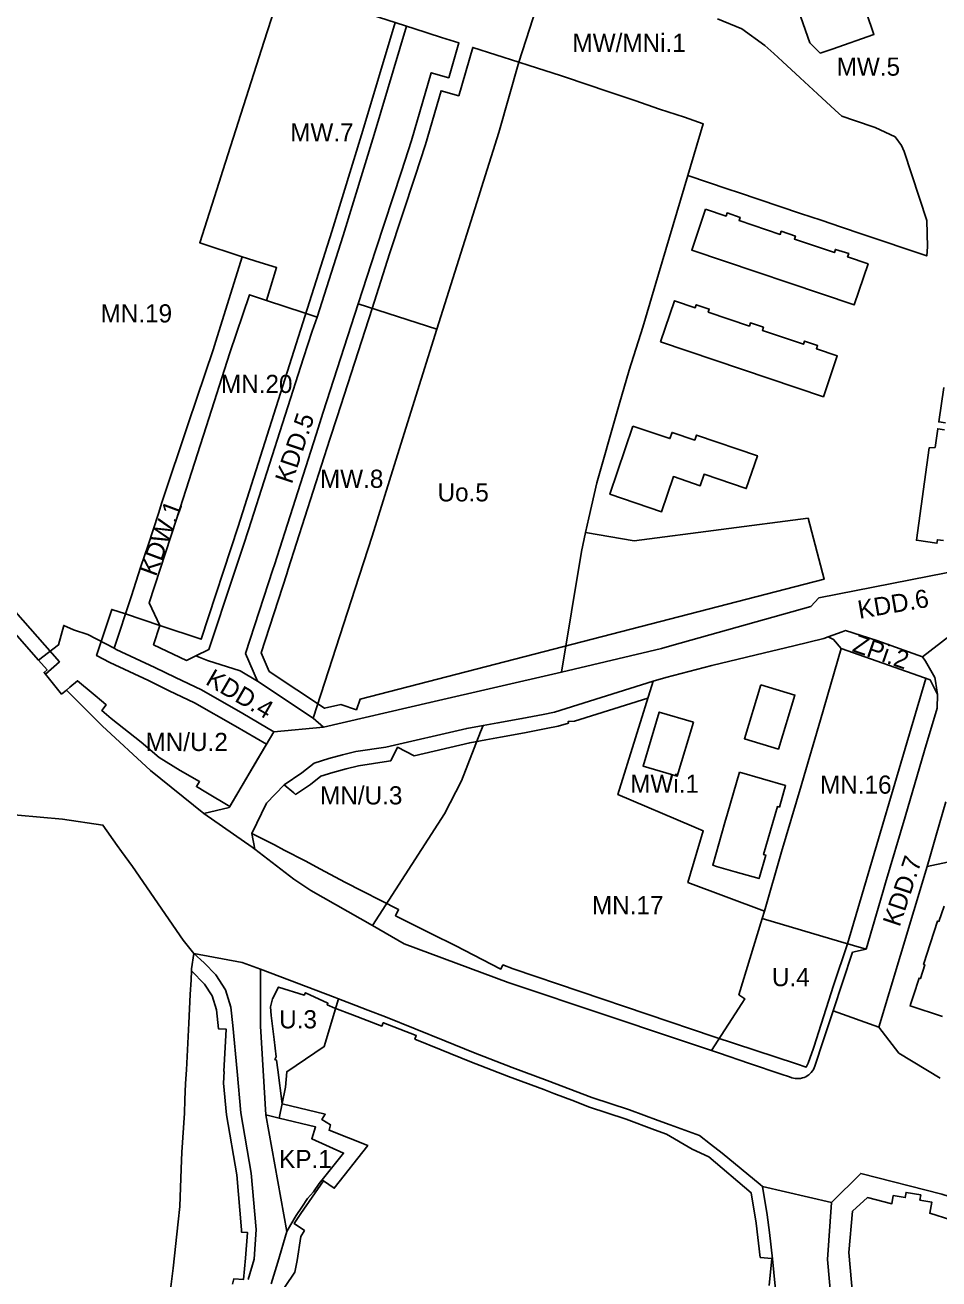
# Model space of a CAD drawing. Extents: x 7416797 to 7419013, y 5549660 to 5551534.
# Drawn here: x 7417362.3 to 7417614, y 5550279.7 to 5550624.8 of the extents above; entities that cross this region are included whole.
import ezdxf

# ---------------------------------------------------------------- set-up
doc = ezdxf.new("R2010")
doc.units = 0
for name, color, linetype in [('LIN_Linia Zabudowy Nieprzekraczalna', 7, 'Continuous'), ('LIN_Linia Zabudowy Obowiązujaca', 7, 'Continuous'), ('LIN_linie_rozgraniczajace', 7, 'Continuous'), ('TXT_Oznaczenia_przeznaczen', 7, 'Continuous')]:
    doc.layers.add(name, color=color, linetype=linetype)

msp = doc.modelspace()

# ---------------------------------------------------------------- linework, layer by layer
at = {"layer": 'LIN_Linia Zabudowy Nieprzekraczalna'}
msp.add_line((7417588.79, 5550371.98), (7417610.35, 5550444.97), dxfattribs=at)
for points in [[(7417399.46, 5550459.54), (7417410.81, 5550455.77), (7417421, 5550486.78), (7417446.8, 5550568.03), (7417455.32, 5550595.79), (7417464.2, 5550625.52)], [(7417498.33, 5550614.61), (7417485.58, 5550618.68), (7417481.74, 5550605.36), (7417476.89, 5550606.74), (7417472.57, 5550591.9), (7417469.74, 5550583.26), (7417462.71, 5550561.83), (7417457.87, 5550546.82), (7417448.23, 5550517.01), (7417446.27, 5550510.88), (7417434.79, 5550475.05), (7417434.37, 5550473.75), (7417427.33, 5550452.02), (7417429.56, 5550446.91), (7417444.81, 5550436.77), (7417449.3, 5550437.84), (7417453.57, 5550436.35), (7417454.55, 5550439.33), (7417582.39, 5550472.29), (7417577.96, 5550489.06), (7417530.06, 5550482.89), (7417516.68, 5550485.17)], [(7417349.45, 5550474.83), (7417371.77, 5550449.57), (7417367.92, 5550446.17), (7417372.39, 5550440.69), (7417373.7, 5550441.79), (7417374.69, 5550442.63), (7417376.78, 5550444.35), (7417381.11, 5550440.74), (7417383.89, 5550438.37), (7417384.67, 5550437.71), (7417383.44, 5550436.2), (7417386.07, 5550433.99), (7417394.27, 5550427.42), (7417399.24, 5550423.21), (7417405.06, 5550419.69), (7417410.36, 5550416.6), (7417409.51, 5550415.23), (7417412.12, 5550413.67), (7417418.66, 5550409.75), (7417426.51, 5550423.06), (7417428.77, 5550426.89), (7417420.29, 5550431.89), (7417409.01, 5550438.31), (7417402, 5550441.62), (7417396.28, 5550444.41), (7417385.68, 5550449.4), (7417382.03, 5550451.29), (7417386.18, 5550464), (7417389.97, 5550462.73)], [(7417533.84, 5550439.59), (7417513.62, 5550433.25), (7417511.91, 5550433.14), (7417511.94, 5550432.72), (7417509.13, 5550431.84), (7417505.81, 5550431.17), (7417499.86, 5550430.02), (7417493.25, 5550428.83), (7417489.2, 5550428.11), (7417484.75, 5550427.31), (7417469.44, 5550423.73), (7417464.89, 5550426.03), (7417463, 5550422.32), (7417462.38, 5550422.18), (7417454.13, 5550420.92), (7417450.7, 5550420.11), (7417447.08, 5550419.1), (7417443.8, 5550418.11), (7417440.92, 5550415.76), (7417436.8, 5550413.09), (7417436.3, 5550413.5), (7417433.63, 5550415.7), (7417428.79, 5550410.62), (7417424.77, 5550402.35), (7417430.99, 5550399.21), (7417433.68, 5550397.69), (7417439.47, 5550394.8), (7417443.69, 5550392.51), (7417450.4, 5550388.88), (7417465.18, 5550381.36), (7417464.34, 5550379.67), (7417474.4, 5550374.57), (7417480.79, 5550371.46), (7417493.34, 5550365), (7417493.91, 5550366.13), (7417496.71, 5550365.1), (7417552.06, 5550346.36), (7417574.77, 5550338.89), (7417577.41, 5550338.03), (7417577.95, 5550339.06), (7417579.39, 5550343.24), (7417579.48, 5550343.51), (7417584.95, 5550360.5), (7417588.79, 5550371.98)], [(7417419.43, 5550278.3), (7417419.84, 5550279.79), (7417422.43, 5550279.53), (7417423.01, 5550285.46), (7417423.58, 5550292.48), (7417421.91, 5550292.63), (7417421.95, 5550293.23), (7417420.59, 5550308.36), (7417417.79, 5550324.87), (7417416.99, 5550333.59), (7417417.19, 5550336.79), (7417417.07, 5550336.8), (7417417.74, 5550348.45), (7417417.51, 5550348.46), (7417415.6, 5550348.53), (7417415.01, 5550353.76), (7417413.88, 5550357.6), (7417411.72, 5550360.86), (7417408.15, 5550364.55)], [(7417567.25, 5550277.89), (7417567.95, 5550285.32), (7417564.76, 5550285.64), (7417563.64, 5550295.1), (7417562.22, 5550303.46), (7417550.62, 5550313.29), (7417545.99, 5550315.45), (7417538.96, 5550319.58), (7417535.69, 5550320.8), (7417527.84, 5550323.69), (7417517.5, 5550327.08), (7417513.58, 5550328.61), (7417507.96, 5550330.76), (7417505.14, 5550331.82), (7417495.47, 5550335.4), (7417484.81, 5550339.52), (7417476.89, 5550342.75), (7417469.67, 5550345.74), (7417470.06, 5550346.74), (7417461.03, 5550350.18), (7417460.93, 5550350.22), (7417460.59, 5550349.33), (7417452.44, 5550352.38), (7417447.62, 5550354.25), (7417445.51, 5550355.16), (7417445.71, 5550355.6), (7417439.5, 5550358.48), (7417439.21, 5550357.84), (7417432.07, 5550360.04), (7417430.42, 5550356.85), (7417429.89, 5550354.57), (7417430.1, 5550352.21), (7417430.9, 5550345.64), (7417431.48, 5550340.87), (7417431.13, 5550340.11), (7417431.6, 5550339.9), (7417431.92, 5550337.27), (7417433.1, 5550327.92), (7417444.97, 5550325.03), (7417444.04, 5550323.56), (7417446.42, 5550322.15), (7417446.02, 5550320.65), (7417456.69, 5550316.41), (7417447.45, 5550304.68), (7417444.47, 5550306.74), (7417438.23, 5550297.72), (7417436.39, 5550295), (7417439.26, 5550293.04), (7417438.23, 5550291.39), (7417437.22, 5550284.78), (7417436.59, 5550281.54), (7417431.12, 5550273.42)], [(7417692.43, 5550272.17), (7417611.45, 5550297.78), (7417611.98, 5550300.89), (7417608.73, 5550301.43), (7417608.96, 5550302.84), (7417604.93, 5550303.53), (7417604.7, 5550302.11), (7417601.39, 5550302.66), (7417601, 5550300.42), (7417594.29, 5550302.09), (7417590.14, 5550298.35), (7417589.15, 5550286.98), (7417595.98, 5550210.57)]]:
    msp.add_lwpolyline(points, dxfattribs=at)
at = {"layer": 'LIN_Linia Zabudowy Obowiązujaca'}
for points in [[(7417563.44, 5550678.69), (7417560.16, 5550677.49), (7417559.27, 5550674.67), (7417578.38, 5550619.91), (7417581.25, 5550617.11), (7417584.57, 5550618.16), (7417596.07, 5550622.21), (7417593.98, 5550628.2), (7417594.83, 5550628.5), (7417593.6, 5550632.03), (7417592.75, 5550631.73), (7417588.77, 5550643.17), (7417589.64, 5550643.47), (7417588.37, 5550647.07), (7417587.51, 5550646.77), (7417583.53, 5550658.19), (7417584.37, 5550658.48), (7417583.15, 5550662.08), (7417582.28, 5550661.78), (7417578.3, 5550673.18), (7417579.15, 5550673.48), (7417577.91, 5550677.07), (7417577.05, 5550676.77), (7417574.97, 5550682.74)], [(7417549.68, 5550574.13), (7417545.89, 5550562.86), (7417590.65, 5550547.78), (7417594.48, 5550559.07), (7417588.81, 5550560.98), (7417589.12, 5550561.9), (7417585.48, 5550563.06), (7417585.19, 5550562.19), (7417574.16, 5550565.9), (7417574.44, 5550566.72), (7417570.54, 5550568.05), (7417570.26, 5550567.21), (7417558.92, 5550571.02), (7417559.21, 5550571.88), (7417555.64, 5550573.09), (7417555.35, 5550572.22)], [(7417537.34, 5550537.61), (7417582.18, 5550522.53), (7417585.95, 5550533.8), (7417580.24, 5550535.73), (7417580.54, 5550536.61), (7417576.94, 5550537.83), (7417576.64, 5550536.95), (7417565.36, 5550540.76), (7417565.66, 5550541.64), (7417562.05, 5550542.84), (7417561.76, 5550541.98), (7417550.43, 5550545.81), (7417550.71, 5550546.63), (7417547.12, 5550547.83), (7417546.85, 5550547.02), (7417541.19, 5550548.93)], [(7417529.67, 5550514.43), (7417523.37, 5550495.67), (7417537.59, 5550490.86), (7417540.86, 5550500.54), (7417548.23, 5550498.04), (7417549.29, 5550501.19), (7417560.93, 5550497.25), (7417563.99, 5550506.27), (7417547.2, 5550511.95), (7417546.74, 5550510.59), (7417540.49, 5550512.7), (7417539.91, 5550511)], [(7417564.96, 5550443.22), (7417560.41, 5550428.41), (7417569.79, 5550425.55), (7417574.31, 5550440.42)], [(7417546.41, 5550432.95), (7417536.97, 5550435.72), (7417532.49, 5550420.86), (7417541.91, 5550418.08)], [(7417559.02, 5550419.16), (7417555.77, 5550407.86), (7417555.05, 5550405.31), (7417551.69, 5550393.58), (7417552.72, 5550393.26), (7417557.88, 5550391.77), (7417564.45, 5550389.92), (7417564.53, 5550390.33), (7417566.27, 5550396.36), (7417565.69, 5550396.53), (7417569.49, 5550409.73), (7417570.06, 5550409.57), (7417571.76, 5550415.53)]]:
    msp.add_lwpolyline(points, close=True, dxfattribs=at)
for points in [[(7417615.29, 5550525.03), (7417613.94, 5550515.58), (7417615.77, 5550515.34)], [(7417615.51, 5550513.42), (7417613.65, 5550513.7), (7417612.89, 5550508.59), (7417611.27, 5550508.44), (7417607.75, 5550483.01), (7417613.43, 5550482.2), (7417613.56, 5550483.14), (7417615.24, 5550482.91)], [(7417615.37, 5550382.35), (7417613.95, 5550378.12), (7417613.61, 5550378.2), (7417610.67, 5550369.12), (7417609.9, 5550366.77), (7417609.74, 5550366.26), (7417610.12, 5550366.14), (7417608.89, 5550362.38), (7417608.51, 5550362.5), (7417608.34, 5550361.98), (7417607.13, 5550358.24), (7417606.15, 5550355.26), (7417606.02, 5550354.87), (7417614.95, 5550351.97)]]:
    msp.add_lwpolyline(points, dxfattribs=at)
at = {"layer": 'LIN_linie_rozgraniczajace'}
for p, q in [((7417389.97, 5550462.73), (7417399.46, 5550459.54)), ((7417609.46, 5550450.96), (7417616.73, 5550456.52)), ((7417430.8, 5550430.33), (7417444.54, 5550431.61)), ((7417584.84, 5550353.48), (7417597.45, 5550348.99)), ((7417432.31, 5550323.99), (7417428.62, 5550324.89)), ((7417434.38, 5550292.78), (7417428.62, 5550324.89)), ((7417565.34, 5550305.12), (7417584.39, 5550300.76)), ((7417434.38, 5550292.78), (7417431.88, 5550284.37)), ((7417431.88, 5550284.37), (7417430.12, 5550278.34))]:
    msp.add_line(p, q, dxfattribs=at)
for points in [[(7417498.33, 5550614.61), (7417507.1, 5550641.98), (7417509.39, 5550649.12), (7417514.34, 5550663.31), (7417519.65, 5550678.48), (7417525.2, 5550694.12), (7417526.2, 5550697.62), (7417529.19, 5550708.08), (7417534.93, 5550728.18), (7417547.88, 5550768.74), (7417550.12, 5550775.76), (7417557.51, 5550797.22), (7417560.89, 5550807.03)], [(7417433.01, 5550635.5), (7417428.17, 5550620.35), (7417416.78, 5550584.76), (7417415.74, 5550581.53), (7417410.4, 5550564.88), (7417422.07, 5550561.06)], [(7417467.36, 5550624.51), (7417464.2, 5550625.52), (7417453.29, 5550629.02), (7417448.7, 5550630.48), (7417444.08, 5550631.96), (7417433.01, 5550635.5)], [(7417553, 5550626.52), (7417559.65, 5550623.75), (7417566.05, 5550619.22), (7417568.47, 5550616.99), (7417570.89, 5550614.76), (7417575.72, 5550610.32), (7417580.55, 5550605.87), (7417585.39, 5550601.42), (7417587.19, 5550599.75), (7417590.75, 5550598.56), (7417596.44, 5550596.64), (7417601.9, 5550594.07), (7417603.7, 5550591.63), (7417604.37, 5550590.06), (7417610.68, 5550571), (7417610.83, 5550563.76), (7417610.6, 5550561.27), (7417592.87, 5550567.25), (7417587.18, 5550569.16), (7417581.5, 5550571.07), (7417575.81, 5550572.99), (7417570.12, 5550574.9), (7417564.44, 5550576.82), (7417558.75, 5550578.73), (7417555.91, 5550579.69), (7417544.83, 5550583.42)], [(7417442.77, 5550544.39), (7417449.93, 5550566.94), (7417458.46, 5550594.73), (7417467.36, 5550624.51)], [(7417454.06, 5550548.05), (7417458.91, 5550563.07), (7417465.94, 5550584.51), (7417468.75, 5550593.08), (7417474.17, 5550611.67), (7417479, 5550610.3), (7417481.77, 5550619.9), (7417477.01, 5550621.43), (7417469.39, 5550623.87), (7417467.36, 5550624.51)], [(7417498.33, 5550614.61), (7417492.82, 5550595.2), (7417488.01, 5550580.14), (7417487.24, 5550577.68), (7417475.69, 5550541.12)], [(7417544.83, 5550583.42), (7417549.06, 5550597.67), (7417543.87, 5550599.42), (7417537.04, 5550601.71), (7417530.22, 5550604.02), (7417523.39, 5550606.31), (7417516.57, 5550608.61), (7417511.38, 5550610.36), (7417509.74, 5550610.89), (7417501.17, 5550613.69), (7417498.33, 5550614.61)], [(7417509.99, 5550446.76), (7417515.51, 5550479.9), (7417516.68, 5550485.17), (7417517.59, 5550489.23), (7417519.74, 5550498.8), (7417525.21, 5550517.86), (7417525.93, 5550520.36), (7417528.66, 5550529.84), (7417532.43, 5550541.7), (7417536.75, 5550556.24), (7417544.83, 5550583.42)], [(7417389.97, 5550462.73), (7417391.52, 5550467.48), (7417394.23, 5550475.81), (7417396.19, 5550481.64), (7417399.09, 5550490.36), (7417400.02, 5550493.38), (7417407.36, 5550515.34), (7417414.07, 5550535.41), (7417414.81, 5550537.81), (7417422.07, 5550561.06)], [(7417422.07, 5550561.06), (7417427.07, 5550559.42), (7417431.57, 5550558.06), (7417428.78, 5550549.04)], [(7417428.78, 5550549.04), (7417424.13, 5550550.58), (7417418.72, 5550534.57), (7417412.2, 5550514.27), (7417405.04, 5550491.97), (7417404.95, 5550491.69), (7417404.02, 5550488.85), (7417396.5, 5550465.82), (7417399.46, 5550459.54)], [(7417426.36, 5550444.23), (7417423.06, 5550451.81), (7417430.56, 5550474.98), (7417430.98, 5550476.28), (7417442.46, 5550512.1), (7417444.42, 5550518.23), (7417454.06, 5550548.05)], [(7417428.78, 5550549.04), (7417439.18, 5550545.59), (7417442.77, 5550544.39)], [(7417454.06, 5550548.05), (7417459.42, 5550546.33), (7417475.69, 5550541.12)], [(7417409.3, 5550451.18), (7417412.88, 5550452.95), (7417419.64, 5550473.14), (7417422.51, 5550481.7), (7417423.89, 5550485.91), (7417439.03, 5550533.23), (7417441.38, 5550540.57), (7417442.77, 5550544.39)], [(7417475.69, 5550541.12), (7417471.36, 5550527.4), (7417464.41, 5550505.06), (7417457.92, 5550484.19), (7417453.23, 5550469.76), (7417441.63, 5550434.08)], [(7417309.69, 5550514.65), (7417320.09, 5550502.64), (7417343.62, 5550475.48), (7417346.44, 5550472.2), (7417366.03, 5550450.02)], [(7417509.99, 5550446.76), (7417537.56, 5550453.2), (7417540.46, 5550454.02), (7417578.72, 5550464.83), (7417580.92, 5550467.15), (7417621.12, 5550475.03), (7417623.13, 5550478.14), (7417658.47, 5550485.31)], [(7417386.89, 5550453.28), (7417388.42, 5550457.98), (7417389.97, 5550462.73)], [(7417366.03, 5550450.02), (7417371.49, 5550454.21), (7417372.99, 5550459.59), (7417375.63, 5550458.33), (7417379.6, 5550457.06), (7417386.89, 5550453.28)], [(7417399.46, 5550459.54), (7417397.72, 5550454.26), (7417406.79, 5550449.94), (7417409.3, 5550451.18)], [(7417583.43, 5550456.4), (7417587.28, 5550457.8), (7417588.23, 5550458.14), (7417596.83, 5550455.4), (7417609.46, 5550450.96)], [(7417535.28, 5550444.24), (7417538.81, 5550445.29), (7417551.4, 5550448.59), (7417560.99, 5550450.86), (7417563.6, 5550451.48), (7417574.03, 5550453.97), (7417582.31, 5550455.98), (7417583.43, 5550456.4)], [(7417587.03, 5550453.21), (7417584.98, 5550455.75), (7417583.43, 5550456.4)], [(7417386.89, 5550453.28), (7417387.45, 5550452.99), (7417398.01, 5550448.02), (7417403.73, 5550445.23), (7417410.86, 5550441.86), (7417422.3, 5550435.35), (7417430.8, 5550430.33)], [(7417409.3, 5550451.18), (7417412.54, 5550449.92), (7417421.52, 5550447.06), (7417426.36, 5550444.23)], [(7417587.03, 5550453.21), (7417581.37, 5550433.64), (7417576.9, 5550418.31), (7417576.02, 5550415.4), (7417570.63, 5550397.24), (7417565.97, 5550380.91)], [(7417613.62, 5550440.55), (7417611.51, 5550444.56), (7417587.03, 5550453.21)], [(7417609.46, 5550450.96), (7417610.28, 5550449.7), (7417612.87, 5550445.28), (7417613.03, 5550444.27), (7417613.62, 5550440.55)], [(7417366.03, 5550450.02), (7417368.39, 5550447.35), (7417367.54, 5550446.63), (7417372.39, 5550440.69), (7417373.7, 5550441.79), (7417383.59, 5550431.94), (7417396.9, 5550419.68), (7417411.59, 5550407.8)], [(7417441.63, 5550434.08), (7417426.36, 5550444.23)], [(7417444.54, 5550431.61), (7417473.79, 5550438.34), (7417509.99, 5550446.76)], [(7417488.5, 5550432.05), (7417492.54, 5550432.77), (7417499.13, 5550433.95), (7417505.03, 5550435.09), (7417508.13, 5550435.72), (7417535.28, 5550444.24)], [(7417535.28, 5550444.24), (7417525.58, 5550413.03), (7417545.85, 5550404.38), (7417549.06, 5550403.01), (7417544.85, 5550388.87), (7417565.97, 5550380.91)], [(7417593.91, 5550370.46), (7417598.54, 5550386.21), (7417599.28, 5550388.72), (7417604.69, 5550406.92), (7417610.04, 5550425.17), (7417613.5, 5550436.82), (7417613.62, 5550440.55)], [(7417444.54, 5550431.61), (7417441.63, 5550434.08)], [(7417430.8, 5550430.33), (7417418.51, 5550409.49), (7417411.59, 5550407.8)], [(7417425.55, 5550398.03), (7417424.77, 5550402.35), (7417428.79, 5550410.62), (7417433.63, 5550415.7), (7417438.56, 5550418.99), (7417441.89, 5550421.71), (7417445.97, 5550422.94), (7417449.71, 5550423.98), (7417453.37, 5550424.85), (7417461.63, 5550426.11), (7417483.94, 5550431.23), (7417488.5, 5550432.05)], [(7417488.5, 5550432.05), (7417487.75, 5550430.25), (7417482.54, 5550416.83), (7417477.83, 5550407.69), (7417457.99, 5550376.95)], [(7417615.9, 5550411), (7417613.24, 5550401.85), (7417611.54, 5550396.09), (7417610.69, 5550393.22)], [(7417408.78, 5550369.31), (7417405.88, 5550372.98), (7417391.88, 5550393.26), (7417388.87, 5550397.33), (7417387.65, 5550399.03), (7417383.74, 5550404.65), (7417372.6, 5550406.27), (7417360.36, 5550407.34), (7417356.11, 5550407.77)], [(7417411.59, 5550407.8), (7417424.84, 5550398.51), (7417425.55, 5550398.03)], [(7417457.99, 5550376.95), (7417440.98, 5550386.66), (7417436.33, 5550389.7), (7417425.55, 5550398.03)], [(7417597.45, 5550348.99), (7417603.41, 5550368.83), (7417610.69, 5550393.22)], [(7417610.69, 5550393.22), (7417616.37, 5550394.41), (7417694.2, 5550367.39), (7417694.76, 5550367.2)], [(7417565.33, 5550378.93), (7417558.87, 5550357.93), (7417560.49, 5550356.83), (7417559.66, 5550355.53), (7417551.33, 5550342.55)], [(7417565.33, 5550378.93), (7417565.97, 5550380.91)], [(7417565.33, 5550378.93), (7417586.95, 5550372.52), (7417593.91, 5550370.46)], [(7417457.99, 5550376.95), (7417466.67, 5550371.98), (7417495.37, 5550361.33), (7417522.81, 5550352.13), (7417540.05, 5550346.34), (7417551.33, 5550342.55)], [(7417336.94, 5550270.27), (7417348.08, 5550266.58), (7417355.33, 5550263.98), (7417362.32, 5550261.63), (7417385.88, 5550253.92), (7417397.94, 5550250.05), (7417400.58, 5550263.54), (7417401.84, 5550273.38), (7417402.48, 5550277.5), (7417403.1, 5550282.66), (7417404.5, 5550295.46), (7417404.9, 5550299.68), (7417405.3, 5550310), (7417405.5, 5550314.62), (7417406.24, 5550325.37), (7417406.27, 5550328.97), (7417406.52, 5550333.54), (7417406.79, 5550337.31), (7417407.4, 5550350.15), (7417407.79, 5550358), (7417408.02, 5550362.03), (7417408.15, 5550364.55), (7417408.17, 5550365.02), (7417408.78, 5550369.31)], [(7417408.78, 5550369.31), (7417422.06, 5550366.85), (7417427.12, 5550364.94)], [(7417423.74, 5550279.56), (7417425.42, 5550285.12), (7417425.96, 5550293.28), (7417424.56, 5550308.87), (7417421.76, 5550325.39), (7417420.71, 5550336.81), (7417419.53, 5550349.46), (7417418.94, 5550354.56), (7417417.55, 5550359.31), (7417414.85, 5550363.38), (7417411.61, 5550366.72), (7417408.78, 5550369.31)], [(7417584.84, 5550353.48), (7417590.2, 5550369.63), (7417593.91, 5550370.46)], [(7417427.12, 5550364.94), (7417447.71, 5550357.18), (7417448.61, 5550356.79)], [(7417428.62, 5550324.89), (7417427.15, 5550349.26), (7417427.12, 5550364.94)], [(7417448.61, 5550356.79), (7417444.69, 5550343.67), (7417434.37, 5550336.74), (7417434.01, 5550332.5), (7417432.31, 5550323.99)], [(7417565.34, 5550305.12), (7417564.73, 5550305.72), (7417554.25, 5550314.34), (7417551.05, 5550316.79), (7417548.07, 5550319.21), (7417539.96, 5550322.12), (7417536.64, 5550323.36), (7417528.74, 5550326.27), (7417518.41, 5550329.65), (7417506.1, 5550334.37), (7417496.44, 5550337.95), (7417485.82, 5550342.06), (7417477.93, 5550345.27), (7417461.61, 5550351.84), (7417456.68, 5550353.71), (7417453.41, 5550354.93), (7417448.61, 5550356.79)], [(7417579.79, 5550338.28), (7417582.2, 5550345.51), (7417584.84, 5550353.48)], [(7417614.32, 5550334.95), (7417602.94, 5550341.82), (7417597.45, 5550348.99)], [(7417551.33, 5550342.55), (7417553.23, 5550341.91), (7417561.76, 5550339.04), (7417570.48, 5550336.11), (7417572.85, 5550335.32), (7417573.46, 5550335.11)], [(7417432.31, 5550323.99), (7417442.32, 5550321.56), (7417441.26, 5550318.29), (7417450.03, 5550314.36), (7417444.91, 5550307.92), (7417443.35, 5550306.01), (7417441.71, 5550303.7), (7417440.1, 5550301.82), (7417438.53, 5550299.43), (7417437.01, 5550297.16), (7417435.5, 5550294.7), (7417434.38, 5550292.78)], [(7417584.39, 5550300.76), (7417592.45, 5550308.74), (7417614.79, 5550303.02), (7417669.2, 5550285.81), (7417698.81, 5550277.72), (7417698.86, 5550277.88), (7417701.9, 5550276.88), (7417701.83, 5550276.67), (7417702.02, 5550276.6), (7417739.04, 5550263.72), (7417856.45, 5550226.59)], [(7417575.59, 5550200.16), (7417573.1, 5550226.53), (7417570.42, 5550259.85), (7417570.64, 5550261.97), (7417570.24, 5550262.01), (7417569.66, 5550269.32), (7417568.17, 5550285.28), (7417567.33, 5550292.47), (7417566.65, 5550297.38), (7417565.34, 5550305.12)], [(7417590.61, 5550203.18), (7417583.29, 5550285.09), (7417584.39, 5550300.76)]]:
    msp.add_lwpolyline(points, dxfattribs=at)
msp.add_arc((7417575.05, 5550339.85), 5, 251.429, 341.631, dxfattribs=at)

# ---------------------------------------------------------------- texts
at = {"layer": 'TXT_Oznaczenia_przeznaczen'}
for s, p in [('MW/MNi.1', (7417513.06, 5550617.42)), ('MW.5', (7417585.81, 5550610.88)), ('MW.7', (7417435.33, 5550592.8)), ('MN.19', (7417383.11, 5550542.96)), ('MN.20', (7417416.26, 5550523.55)), ('MW.8', (7417443.52, 5550497.44)), ('Uo.5', (7417475.9, 5550493.71)), ('MN/U.2', (7417395.49, 5550425.02)), ('MWi.1', (7417528.96, 5550413.51)), ('MN.16', (7417581.23, 5550413.27)), ('MN/U.3', (7417443.56, 5550410.31)), ('MN.17', (7417518.42, 5550380.07)), ('U.4', (7417567.98, 5550360.29)), ('U.3', (7417432.29, 5550348.68)), ('KP.1', (7417432.29, 5550310.22))]:
    msp.add_text(s, height=5, dxfattribs=at).set_placement(p)
for s, rotation, p in [('KDD.5', 71.3304, (7417435.76, 5550498.29)), ('KDW.1', 69.6607, (7417398.32, 5550472.83)), ('KDD.6', 9.7723, (7417592.07, 5550461.38)), ('ZPi.2', 340.8495, (7417589.84, 5550452.53)), ('KDD.4', 329.8801, (7417411.72, 5550443.53)), ('KDD.7', 71.4807, (7417603.13, 5550376.39))]:
    msp.add_text(s, height=5, rotation=rotation, dxfattribs=at).set_placement(p)

doc.saveas('drawing.dxf')
